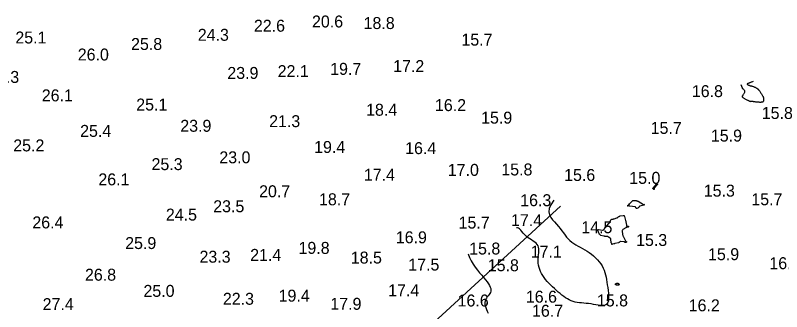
# Model space of a CAD drawing. Extents: x 3040093 to 3056816, y 408076 to 509144.
# Drawn here: x 3044904.9 to 3045225.6, y 434097.2 to 434221.2 of the extents above; entities that cross this region are included whole.
import ezdxf

# ---------------------------------------------------------------- set-up
doc = ezdxf.new("R2010")
doc.units = 0
for name, color, linetype in [('V-CHAN-CONT-EL15', 7, 'Continuous'), ('V-CHAN-CONT-EL17', 7, 'Continuous'), ('V-TOPO-SOUN-0610', 7, 'Continuous'), ('V-TOPO-SOUN-0810', 7, 'Continuous'), ('V-TOPO-SOUN-EXSS', 7, 'Continuous')]:
    doc.layers.add(name, color=color, linetype=linetype)

msp = doc.modelspace()

# ---------------------------------------------------------------- linework, layer by layer
at = {"layer": 'V-CHAN-CONT-EL15'}
for points in [[(3045173.48, 434150.75), (3045173.49, 434150.75), (3045173.49, 434150.75), (3045173.5, 434150.75), (3045173.52, 434150.72), (3045173.52, 434150.71), (3045173.53, 434150.7), (3045173.53, 434150.7), (3045173.53, 434150.69), (3045173.6, 434150.52), (3045173.61, 434150.49), (3045173.6, 434150.46), (3045173.6, 434150.44), (3045173.58, 434150.41), (3045172.22, 434148.83), (3045172.19, 434148.78), (3045172.17, 434148.73), (3045172.15, 434148.68), (3045172.15, 434148.63), (3045172.16, 434148.39), (3045172.16, 434148.35), (3045172.15, 434148.33), (3045172.13, 434148.34), (3045172.1, 434148.37), (3045171.85, 434148.65), (3045171.84, 434148.66), (3045171.82, 434148.67), (3045171.81, 434148.68), (3045171.79, 434148.68), (3045171.71, 434148.67), (3045171.7, 434148.67), (3045171.69, 434148.68), (3045171.69, 434148.69), (3045171.7, 434148.7), (3045171.78, 434148.77), (3045171.79, 434148.79), (3045171.81, 434148.81), (3045171.83, 434148.83), (3045171.84, 434148.85), (3045173.4, 434150.66), (3045173.4, 434150.66), (3045173.41, 434150.67), (3045173.41, 434150.68), (3045173.42, 434150.68), (3045173.44, 434150.71), (3045173.44, 434150.72), (3045173.45, 434150.72), (3045173.45, 434150.73), (3045173.46, 434150.73), (3045173.48, 434150.75)], [(3045168.04, 434141.92), (3045168.05, 434141.9), (3045168.04, 434141.89), (3045168.04, 434141.88), (3045168.01, 434141.82), (3045168, 434141.81), (3045167.99, 434141.8), (3045167.97, 434141.79), (3045167.96, 434141.78), (3045166.26, 434141.38), (3045166.19, 434141.35), (3045166.12, 434141.32), (3045166.06, 434141.27), (3045166.01, 434141.2), (3045165.83, 434140.93), (3045165.78, 434140.87), (3045165.72, 434140.81), (3045165.66, 434140.76), (3045165.59, 434140.72), (3045164.9, 434140.35), (3045164.82, 434140.32), (3045164.76, 434140.33), (3045164.71, 434140.37), (3045164.67, 434140.44), (3045164.54, 434140.81), (3045164.49, 434140.89), (3045164.44, 434140.96), (3045164.36, 434141), (3045164.28, 434141.03), (3045162.1, 434141.36), (3045161.98, 434141.38), (3045161.86, 434141.39), (3045161.74, 434141.4), (3045161.61, 434141.41), (3045161.05, 434141.44), (3045160.98, 434141.45), (3045160.96, 434141.47), (3045160.97, 434141.5), (3045161.03, 434141.54), (3045161.34, 434141.72), (3045161.41, 434141.77), (3045161.49, 434141.82), (3045161.55, 434141.88), (3045161.62, 434141.94), (3045161.95, 434142.3), (3045162.02, 434142.38), (3045162.1, 434142.46), (3045162.17, 434142.55), (3045162.24, 434142.63), (3045162.99, 434143.48), (3045163.15, 434143.62), (3045163.33, 434143.72), (3045163.52, 434143.77), (3045163.74, 434143.77), (3045164.63, 434143.67), (3045164.85, 434143.63), (3045165.06, 434143.57), (3045165.27, 434143.49), (3045165.47, 434143.39), (3045167.8, 434142.01), (3045167.82, 434142), (3045167.84, 434142), (3045167.85, 434142.01), (3045167.87, 434142.02), (3045167.92, 434142.1), (3045167.94, 434142.12), (3045167.95, 434142.12), (3045167.96, 434142.12), (3045167.97, 434142.1), (3045168.04, 434141.93)], [(3045160.54, 434126.59), (3045160.56, 434126.56), (3045160.58, 434126.53), (3045160.58, 434126.49), (3045160.57, 434126.31), (3045160.56, 434126.28), (3045160.54, 434126.25), (3045160.51, 434126.23), (3045160.48, 434126.21), (3045160.09, 434126.15), (3045160.06, 434126.15), (3045160.03, 434126.16), (3045160.01, 434126.17), (3045159.99, 434126.2), (3045159.91, 434126.31), (3045159.89, 434126.33), (3045159.87, 434126.35), (3045159.84, 434126.36), (3045159.81, 434126.37), (3045158.13, 434126.54), (3045158.05, 434126.54), (3045157.98, 434126.53), (3045157.91, 434126.49), (3045157.85, 434126.44), (3045157.62, 434126.21), (3045157.56, 434126.16), (3045157.49, 434126.12), (3045157.42, 434126.08), (3045157.34, 434126.06), (3045155.82, 434125.7), (3045155.71, 434125.67), (3045155.6, 434125.64), (3045155.48, 434125.62), (3045155.37, 434125.59), (3045154.73, 434125.42), (3045154.71, 434125.42), (3045154.7, 434125.41), (3045154.68, 434125.41), (3045154.67, 434125.4), (3045154.6, 434125.38), (3045154.59, 434125.38), (3045154.58, 434125.38), (3045154.56, 434125.38), (3045154.55, 434125.39), (3045154.49, 434125.48), (3045154.47, 434125.5), (3045154.46, 434125.52), (3045154.45, 434125.54), (3045154.44, 434125.56), (3045154.32, 434125.92), (3045154.3, 434125.99), (3045154.29, 434126.06), (3045154.28, 434126.13), (3045154.27, 434126.2), (3045154.15, 434127.35), (3045154.12, 434127.53), (3045154.05, 434127.7), (3045153.94, 434127.84), (3045153.8, 434127.96), (3045153.13, 434128.44), (3045152.99, 434128.53), (3045152.83, 434128.6), (3045152.67, 434128.65), (3045152.5, 434128.67), (3045151.8, 434128.72), (3045151.63, 434128.73), (3045151.45, 434128.75), (3045151.28, 434128.79), (3045151.11, 434128.82), (3045149.91, 434129.12), (3045149.84, 434129.14), (3045149.77, 434129.18), (3045149.7, 434129.22), (3045149.64, 434129.27), (3045149.42, 434129.5), (3045149.37, 434129.56), (3045149.32, 434129.62), (3045149.28, 434129.69), (3045149.25, 434129.76), (3045148.65, 434131.11), (3045148.58, 434131.33), (3045148.61, 434131.47), (3045148.74, 434131.53), (3045148.96, 434131.53), (3045150.63, 434131.27), (3045150.74, 434131.27), (3045150.84, 434131.29), (3045150.93, 434131.34), (3045151.01, 434131.42), (3045151.3, 434131.79), (3045151.37, 434131.88), (3045151.44, 434131.97), (3045151.52, 434132.06), (3045151.59, 434132.15), (3045153.24, 434134.06), (3045153.37, 434134.22), (3045153.49, 434134.39), (3045153.6, 434134.57), (3045153.7, 434134.76), (3045154.15, 434135.67), (3045154.22, 434135.76), (3045154.3, 434135.84), (3045154.39, 434135.89), (3045154.51, 434135.91), (3045154.99, 434135.97), (3045155.11, 434135.99), (3045155.23, 434136.01), (3045155.35, 434136.04), (3045155.47, 434136.08), (3045156.58, 434136.48), (3045156.71, 434136.53), (3045156.83, 434136.59), (3045156.95, 434136.65), (3045157.06, 434136.73), (3045157.5, 434137.04), (3045157.62, 434137.11), (3045157.74, 434137.17), (3045157.86, 434137.21), (3045157.99, 434137.24), (3045159.2, 434137.45), (3045159.42, 434137.45), (3045159.6, 434137.39), (3045159.73, 434137.26), (3045159.81, 434137.05), (3045160.26, 434135.31), (3045160.31, 434135.07), (3045160.37, 434134.83), (3045160.41, 434134.59), (3045160.45, 434134.35), (3045160.65, 434133.09), (3045160.68, 434133.01), (3045160.72, 434132.96), (3045160.78, 434132.94), (3045160.86, 434132.94), (3045161.31, 434133.03), (3045161.35, 434133.03), (3045161.39, 434133.02), (3045161.41, 434132.99), (3045161.43, 434132.95), (3045161.48, 434132.75), (3045161.48, 434132.7), (3045161.47, 434132.67), (3045161.44, 434132.65), (3045161.4, 434132.63), (3045160.74, 434132.52), (3045160.62, 434132.49), (3045160.5, 434132.45), (3045160.39, 434132.4), (3045160.29, 434132.33), (3045159.17, 434131.53), (3045159, 434131.36), (3045158.88, 434131.18), (3045158.82, 434130.96), (3045158.83, 434130.72), (3045158.96, 434129.71), (3045159, 434129.46), (3045159.07, 434129.22), (3045159.15, 434128.98), (3045159.25, 434128.75), (3045160.24, 434126.8), (3045160.26, 434126.77), (3045160.29, 434126.74), (3045160.32, 434126.71), (3045160.35, 434126.69), (3045160.51, 434126.61)]]:
    msp.add_lwpolyline(points, close=True, dxfattribs=at)
at = {"layer": 'V-CHAN-CONT-EL17'}
for points in [[(3045213.62, 434193.53), (3045213.3, 434193.4), (3045213, 434193.28), (3045212.75, 434193.16), (3045212.51, 434193.06), (3045212.31, 434192.96), (3045212.12, 434192.88), (3045211.94, 434192.8), (3045211.78, 434192.74), (3045211.62, 434192.69), (3045211.48, 434192.65), (3045211.35, 434192.61), (3045211.25, 434192.57), (3045211.16, 434192.54), (3045211.11, 434192.5), (3045211.1, 434192.45), (3045211.12, 434192.4), (3045211.18, 434192.33), (3045211.28, 434192.25), (3045211.42, 434192.17), (3045211.57, 434192.08), (3045211.73, 434192), (3045211.91, 434191.92), (3045212.08, 434191.85), (3045212.24, 434191.79), (3045212.39, 434191.74), (3045212.53, 434191.71), (3045212.67, 434191.68), (3045212.8, 434191.66), (3045212.93, 434191.63), (3045213.07, 434191.6), (3045213.23, 434191.56), (3045213.4, 434191.51), (3045213.59, 434191.44), (3045213.8, 434191.36), (3045214.02, 434191.27), (3045214.24, 434191.17), (3045214.45, 434191.07), (3045214.66, 434190.97), (3045214.86, 434190.87), (3045215.03, 434190.78), (3045215.18, 434190.69), (3045215.3, 434190.62), (3045215.4, 434190.55), (3045215.48, 434190.49), (3045215.54, 434190.44), (3045215.6, 434190.39), (3045215.65, 434190.35), (3045215.69, 434190.31), (3045215.72, 434190.27), (3045215.76, 434190.23), (3045215.81, 434190.18), (3045215.86, 434190.12), (3045215.92, 434190.04), (3045216, 434189.94), (3045216.1, 434189.8), (3045216.23, 434189.63), (3045216.37, 434189.42), (3045216.54, 434189.18), (3045216.72, 434188.92), (3045216.91, 434188.64), (3045217.1, 434188.35), (3045217.27, 434188.07), (3045217.44, 434187.81), (3045217.58, 434187.57), (3045217.69, 434187.36), (3045217.79, 434187.18), (3045217.86, 434187.02), (3045217.91, 434186.87), (3045217.94, 434186.74), (3045217.97, 434186.61), (3045217.99, 434186.47), (3045218, 434186.33), (3045218.01, 434186.17), (3045218.01, 434186), (3045218.01, 434185.83), (3045218, 434185.66), (3045217.98, 434185.49), (3045217.95, 434185.34), (3045217.9, 434185.2), (3045217.83, 434185.08), (3045217.74, 434184.98), (3045217.64, 434184.91), (3045217.51, 434184.86), (3045217.37, 434184.82), (3045217.21, 434184.8), (3045217.04, 434184.79), (3045216.84, 434184.78), (3045216.64, 434184.78), (3045216.42, 434184.78), (3045216.19, 434184.79), (3045215.96, 434184.79), (3045215.71, 434184.8), (3045215.46, 434184.82), (3045215.21, 434184.84), (3045214.96, 434184.86), (3045214.71, 434184.89), (3045214.47, 434184.93), (3045214.23, 434184.97), (3045214.01, 434185.01), (3045213.79, 434185.06), (3045213.59, 434185.1), (3045213.4, 434185.13), (3045213.23, 434185.16), (3045213.08, 434185.17), (3045212.96, 434185.17), (3045212.85, 434185.16), (3045212.75, 434185.14), (3045212.67, 434185.12), (3045212.6, 434185.1), (3045212.54, 434185.08), (3045212.49, 434185.07), (3045212.43, 434185.06), (3045212.38, 434185.07), (3045212.31, 434185.08), (3045212.24, 434185.11), (3045212.16, 434185.16), (3045212.06, 434185.22), (3045211.93, 434185.29), (3045211.78, 434185.38), (3045211.6, 434185.49), (3045211.38, 434185.61), (3045211.14, 434185.74), (3045210.89, 434185.88), (3045210.62, 434186.03), (3045210.36, 434186.17), (3045210.12, 434186.32), (3045209.89, 434186.45), (3045209.69, 434186.58), (3045209.53, 434186.68), (3045209.41, 434186.78), (3045209.31, 434186.86), (3045209.25, 434186.93), (3045209.2, 434187), (3045209.18, 434187.06), (3045209.17, 434187.12), (3045209.16, 434187.17), (3045209.17, 434187.23), (3045209.18, 434187.29), (3045209.2, 434187.37), (3045209.24, 434187.45), (3045209.28, 434187.54), (3045209.35, 434187.66), (3045209.42, 434187.8), (3045209.52, 434187.96), (3045209.64, 434188.15), (3045209.76, 434188.36), (3045209.89, 434188.59), (3045210, 434188.82), (3045210.1, 434189.04), (3045210.16, 434189.26), (3045210.18, 434189.46), (3045210.14, 434189.64), (3045210.05, 434189.79), (3045209.9, 434189.93), (3045209.72, 434190.09), (3045209.51, 434190.29), (3045209.28, 434190.57), (3045209.06, 434190.94), (3045208.84, 434191.44), (3045208.65, 434192.1)], [(3045130.27, 434143.83), (3045129.01, 434141.96), (3045128.34, 434140.34), (3045128.17, 434138.94), (3045128.4, 434137.72), (3045128.93, 434136.64), (3045129.67, 434135.66), (3045130.51, 434134.73), (3045131.38, 434133.83), (3045132.18, 434132.91), (3045132.92, 434131.98), (3045133.61, 434131.06), (3045134.27, 434130.16), (3045134.92, 434129.28), (3045135.58, 434128.44), (3045136.27, 434127.66), (3045136.99, 434126.94), (3045137.77, 434126.3), (3045138.6, 434125.72), (3045139.47, 434125.18), (3045140.37, 434124.66), (3045141.3, 434124.16), (3045142.24, 434123.65), (3045143.19, 434123.12), (3045144.13, 434122.54), (3045145.07, 434121.91), (3045145.98, 434121.23), (3045146.86, 434120.51), (3045147.69, 434119.74), (3045148.48, 434118.93), (3045149.2, 434118.1), (3045149.84, 434117.24), (3045150.41, 434116.36), (3045150.88, 434115.47), (3045151.27, 434114.56), (3045151.59, 434113.62), (3045151.85, 434112.66), (3045152.07, 434111.66), (3045152.27, 434110.63), (3045152.44, 434109.55), (3045152.61, 434108.43), (3045152.78, 434107.26), (3045152.94, 434106.07), (3045153.07, 434104.89), (3045153.14, 434103.77), (3045153.14, 434102.72), (3045153.04, 434101.79), (3045152.83, 434101.01), (3045152.47, 434100.4), (3045151.97, 434100.01), (3045151.33, 434099.79), (3045150.57, 434099.73), (3045149.72, 434099.78), (3045148.79, 434099.91), (3045147.82, 434100.09), (3045146.81, 434100.28), (3045145.79, 434100.46), (3045144.79, 434100.59), (3045143.79, 434100.69), (3045142.82, 434100.77), (3045141.86, 434100.85), (3045140.93, 434100.94), (3045140.02, 434101.06), (3045139.13, 434101.22), (3045138.28, 434101.45), (3045137.46, 434101.74), (3045136.66, 434102.11), (3045135.88, 434102.54), (3045135.11, 434103.03), (3045134.35, 434103.57), (3045133.6, 434104.15), (3045132.84, 434104.78), (3045132.07, 434105.44), (3045131.28, 434106.13), (3045130.49, 434106.84), (3045129.7, 434107.58), (3045128.93, 434108.33), (3045128.18, 434109.11), (3045127.46, 434109.9), (3045126.78, 434110.71), (3045126.16, 434111.52), (3045125.6, 434112.35), (3045125.1, 434113.19), (3045124.67, 434114.03), (3045124.31, 434114.89), (3045124.02, 434115.75), (3045123.8, 434116.62), (3045123.67, 434117.5), (3045123.61, 434118.39), (3045123.63, 434119.28), (3045123.7, 434120.17), (3045123.8, 434121.04), (3045123.9, 434121.89), (3045123.96, 434122.7), (3045123.96, 434123.46), (3045123.86, 434124.17), (3045123.65, 434124.8), (3045123.29, 434125.36), (3045122.81, 434125.86), (3045122.23, 434126.32), (3045121.58, 434126.76), (3045120.87, 434127.2), (3045120.14, 434127.66), (3045119.42, 434128.16), (3045118.72, 434128.73), (3045118.06, 434129.36), (3045117.46, 434130.04), (3045116.89, 434130.7), (3045116.36, 434131.31), (3045115.87, 434131.81), (3045115.41, 434132.16), (3045114.97, 434132.32), (3045114.55, 434132.23)], [(3045094.43, 434121.39), (3045095, 434119.91), (3045095.69, 434118.49), (3045096.49, 434117.14), (3045097.35, 434115.85), (3045098.25, 434114.63), (3045099.16, 434113.49), (3045100.04, 434112.42), (3045100.87, 434111.42), (3045101.61, 434110.5), (3045102.27, 434109.65), (3045102.82, 434108.87), (3045103.27, 434108.15), (3045103.61, 434107.49), (3045103.83, 434106.87), (3045103.92, 434106.3), (3045103.89, 434105.78), (3045103.72, 434105.28), (3045103.45, 434104.81), (3045103.11, 434104.35), (3045102.73, 434103.88), (3045102.34, 434103.4), (3045101.98, 434102.9), (3045101.67, 434102.36), (3045101.46, 434101.76), (3045101.36, 434101.11), (3045101.38, 434100.41), (3045101.49, 434099.67), (3045101.71, 434098.91), (3045102, 434098.14), (3045102.36, 434097.36), (3045102.78, 434096.6)]]:
    msp.add_lwpolyline(points, dxfattribs=at)
msp.add_lwpolyline([(3045156.14, 434108.93), (3045156.17, 434108.97), (3045156.21, 434108.99), (3045156.26, 434109.02), (3045156.32, 434109.03), (3045156.38, 434109.05), (3045156.44, 434109.06), (3045156.52, 434109.08), (3045156.6, 434109.09), (3045156.69, 434109.1), (3045156.78, 434109.1), (3045156.87, 434109.1), (3045156.96, 434109.09), (3045157.05, 434109.07), (3045157.14, 434109.04), (3045157.23, 434109), (3045157.31, 434108.94), (3045157.38, 434108.87), (3045157.44, 434108.79), (3045157.49, 434108.71), (3045157.52, 434108.63), (3045157.52, 434108.55), (3045157.51, 434108.48), (3045157.47, 434108.42), (3045157.4, 434108.37), (3045157.31, 434108.34), (3045157.2, 434108.32), (3045157.08, 434108.31), (3045156.95, 434108.31), (3045156.82, 434108.31), (3045156.69, 434108.32), (3045156.58, 434108.33), (3045156.47, 434108.34), (3045156.39, 434108.36), (3045156.31, 434108.37), (3045156.25, 434108.39), (3045156.2, 434108.41), (3045156.16, 434108.44), (3045156.12, 434108.47), (3045156.1, 434108.51), (3045156.08, 434108.55), (3045156.06, 434108.6), (3045156.06, 434108.65), (3045156.05, 434108.7), (3045156.06, 434108.76), (3045156.07, 434108.81), (3045156.09, 434108.85), (3045156.11, 434108.9)], close=True, dxfattribs=at)
at = {"layer": 'V-TOPO-SOUN-EXSS'}
msp.add_line((3044745.73, 433786.68), (3045133.04, 434141.35), dxfattribs=at)

# ---------------------------------------------------------------- texts
at = {"layer": 'V-TOPO-SOUN-0610'}
for s, p in [('16.8 ', (3045187.98, 434186.97)), ('15.8 ', (3045217.24, 434177.82)), ('15.7 ', (3045170.75, 434171.59)), ('15.9 ', (3045195.95, 434168.37)), ('15.6 ', (3045134.53, 434151.9)), ('15.0 ', (3045161.8, 434150.69)), ('15.3 ', (3045192.97, 434145.34)), ('16.3 ', (3045116.16, 434141.34)), ('15.7 ', (3045212.88, 434141.73)), ('14.5 ', (3045141.72, 434130.05)), ('15.3 ', (3045164.65, 434124.7)), ('17.1 ', (3045120.56, 434119.85)), ('15.9 ', (3045194.77, 434118.76)), ('16.0 ', (3045220.43, 434114.99)), ('16.6 ', (3045089.95, 434099.38)), ('15.8 ', (3045148.25, 434099.41)), ('16.2 ', (3045186.67, 434097.37))]:
    msp.add_text(s, height=5, dxfattribs=at).set_placement(p)
at = {"layer": 'V-TOPO-SOUN-0810'}
for s, p in [('22.6 ', (3045004.71, 434214.34)), ('20.6 ', (3045029.02, 434216.11)), ('18.8 ', (3045050.61, 434215.45)), ('24.3 ', (3044981.22, 434210.53)), ('25.1 ', (3044904.88, 434209.41)), ('15.7 ', (3045091.55, 434208.53)), ('25.8 ', (3044953.3, 434206.69)), ('26.0 ', (3044930.99, 434202.29)), ('17.2 ', (3045062.98, 434197.44)), ('23.9 ', (3044993.59, 434194.58)), ('22.1 ', (3045014.65, 434195.34)), ('19.7 ', (3045036.63, 434196.29)), ('25.3 ', (3044893.46, 434192.91)), ('26.1 ', (3044915.93, 434185.2)), ('25.1 ', (3044955.47, 434181.36)), ('18.4 ', (3045051.66, 434179.17)), ('16.2 ', (3045080.47, 434181.13)), ('15.9 ', (3045099.79, 434175.88)), ('23.9 ', (3044973.9, 434172.47)), ('21.3 ', (3045011.08, 434174.41)), ('25.4 ', (3044931.98, 434170.34)), ('25.2 ', (3044903.99, 434164.27)), ('19.4 ', (3045029.91, 434163.61)), ('16.4 ', (3045068, 434163.12)), ('23.0 ', (3044990.24, 434159.28)), ('25.3 ', (3044961.86, 434156.43)), ('17.0 ', (3045085.85, 434154.03)), ('15.8 ', (3045108.25, 434154.2)), ('26.1 ', (3044939.62, 434150.06)), ('17.4 ', (3045050.71, 434151.97)), ('20.7 ', (3045006.88, 434145.08)), ('18.7 ', (3045031.97, 434141.73)), ('23.5 ', (3044987.68, 434138.81)), ('24.5 ', (3044967.87, 434135.33)), ('26.4 ', (3044911.99, 434132.05)), ('15.7 ', (3045090.37, 434131.99)), ('17.4 ', (3045112.32, 434133)), ('16.9 ', (3045064.09, 434125.82)), ('25.9 ', (3044950.84, 434123.42)), ('19.8 ', (3045023.38, 434121.39)), ('23.3 ', (3044981.94, 434117.71)), ('21.4 ', (3045003.14, 434118.47)), ('18.5 ', (3045045.26, 434117.35)), ('15.8 ', (3045102.58, 434114.14)), ('26.8 ', (3044934.01, 434110.17)), ('25.0 ', (3044958.48, 434103.41)), ('19.4 ', (3045015.05, 434101.41)), ('17.4 ', (3045060.88, 434103.67)), ('27.4 ', (3044916.29, 434097.87)), ('22.3 ', (3044991.72, 434100.1)), ('17.9 ', (3045036.7, 434098)), ('16.6 ', (3045118.52, 434100.98))]:
    msp.add_text(s, height=5, dxfattribs=at).set_placement(p)
at = {"layer": 'V-TOPO-SOUN-EXSS'}
for s, p in [('15.8 ', (3045094.8, 434121.13)), ('17.5 ', (3045069.31, 434114.43)), ('16.7 ', (3045121.08, 434095.1))]:
    msp.add_text(s, height=5, dxfattribs=at).set_placement(p)

doc.saveas('drawing.dxf')
